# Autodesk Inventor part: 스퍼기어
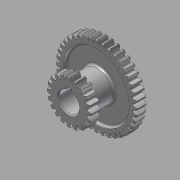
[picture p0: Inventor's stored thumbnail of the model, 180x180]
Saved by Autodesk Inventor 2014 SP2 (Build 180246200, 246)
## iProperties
Created: 2015-09
Part Number: 스퍼기어
Material: 강철, 연강
Document SubType Name: Modeling
Designer: mduedu
Density: 1 g/cm^3
Appearance: 강철
Author: mduedu
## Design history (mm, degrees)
sketch "스케치1"
  geometry: C1 r 38 at (0, 0); C2 r 40 at (0, 0); C3 r 35.5 at (0, 0); 1 further point
  constraints: 3 centre point, 3 coincident
  dimensions: "d0" = 76 diameter of C1; "d2" = 2 radial gap between concentric circles of C2 C1; "d3" = 71 diameter of C3 (computed from d0)
extrude "돌출1" new body sketch "스케치1" stored distance "d4" = 10; taper "d5" = 0 deg
sketch "스케치2"
  geometry: L1 (0, 35.5)-(0, -35.5); L2 (0, 0)-(40, 0); L3 (0, 0.57)-(39.996, 0.57); L4 (0, 1.57)-(39.969, 1.57); L5 (0, 2.07)-(39.946, 2.07); A1 r 35.5 centre (0, 0) between (0, 35.5) and (0, -35.5) reference; A2 r 40 centre (0, 0) between (40, 0) and (39.946, 2.07) reference; A3 r 9.234 centre (34.93, -7.149) between (39.996, 0.57) and (35.44, 2.07); A4 r 9.234 centre (34.93, 7.149) between (35.44, -2.07) and (39.996, -0.57); A5 r 40 centre (0, 0) between (39.996, -0.57) and (39.996, 0.57); A6 r 35.5 centre (0, 0) between (35.44, -2.07) and (35.44, 2.07); 4 further points
  constraints: 16 point on circle, 10 end point, 6 point on line, 4 centre point, 3 coincident, 3 parallel, 3 symmetric about line, 2 midpoint, 1 perpendicular, 1 vertical, 3 other
  dimensions: "d6" = 0.5 distance between parallel lines of L4 L5; "d8" = 1 distance between parallel lines of L3 L4; "d9" = 1.57 distance between parallel lines of L2 L4
extrude "돌출2" join sketch "스케치2" distance "d10" = 5; taper "d12" = 0 deg; dims "d11" = 5, "d13" = 0
fillet "모깎기1" dims "d17" = 0.5
chamfer "모따기1" distance "d21" = 1; stored, may be unused: second distance "d22" = 2, angle "d23" = 45 deg
sketch "스케치3"
  geometry: C1 r 32.5 at (0, 0); C2 r 15 at (0, 0); 1 further point
  constraints: 2 centre point, 2 coincident
  dimensions: "d27" = 65 diameter of C1; "d28" = 30 diameter of C2
extrude "돌출3" cut sketch "스케치3" distance "d29" = 3; taper "d30" = 0 deg
fillet "모깎기2" dims "d31" = 2
node "작업 평면2"
  node "작업 평면1"
sketch "스케치4"
  geometry: C1 r 15 at (0, 0) reference; 1 further point
extrude "돌출4" join sketch "스케치4" stored distance "d34" = 3; taper "d35" = 0 deg
sketch "스케치5"
  geometry: C1 r 17.5 at (0, 0); C2 r 20 at (0, 0); C3 r 22 at (0, 0); 1 further point
  constraints: 3 centre point, 3 coincident
  dimensions: "d36" = 40 diameter of C2; "d38" = 2 radial gap between concentric circles of C2 C3; "d39" = 35 diameter of C1 (= d36 - 2.5 x d38)
extrude "돌출6" join sketch "스케치5" distance "d46" = 10; taper "d47" = 0 deg
sketch "스케치6"
  geometry: L1 (0, 0)-(0, 22); L2 (-17.5, 0)-(17.5, 0); L3 (-0.57, 0)-(-0.57, 21.993); L4 (-1.57, 0)-(-1.57, 21.944); L5 (-2.07, 0)-(-2.07, 21.902); A1 r 22 centre (0, 0) between (0, 22) and (-0.57, 21.993) reference; A2 r 17.5 centre (0, 0) between (-17.5, 0) and (17.5, 0) reference; A3 r 9.431 centre (7.348, 16.868) between (-0.57, 21.993) and (-2.07, 17.377); A4 r 9.431 centre (-7.348, 16.868) between (2.07, 17.377) and (0.57, 21.993); A5 r 17.5 centre (0, 0) between (2.07, 17.377) and (-2.07, 17.377); A6 r 22 centre (0, 0) between (0.57, 21.993) and (-0.57, 21.993); 4 further points
  constraints: 16 point on circle, 10 end point, 5 point on line, 4 centre point, 3 coincident, 3 symmetric about line, 2 parallel, 2 perpendicular, 1 midpoint, 1 vertical, 3 other
  dimensions: "d40" = 0.5 distance between parallel lines of L4 L5; "d42" = 1 distance between parallel lines of L3 L4; "d43" = 1.57 distance between parallel lines of L1 L4
extrude "돌출5" join sketch "스케치6" distance "d44" = 10; taper "d45" = 0 deg
fillet "모깎기3" dims "d48" = 0.5
chamfer "모따기2" distance "d49" = 1; stored, may be unused: second distance "d50" = 2, angle "d51" = 45 deg
sketch "스케치7"
  geometry: C1 r 10 at (0, 0); 1 further point
  constraints: 1 centre point, 1 coincident
  dimensions: "d55" = 20 diameter of C1
extrude "돌출7" cut sketch "스케치7" stored distance "d56" = 10; taper "d57" = 0 deg
sketch "스케치8"
  geometry: L1 (-9.539, -3)-(-12.8, -3); L2 (-12.8, -3)-(-12.8, 3); L3 (-12.8, 3)-(-9.539, 3); L4 (-9.539, 3)-(-9.539, -3); A1 r 10 centre (0, 0) between (-9.539, -3) and (-9.539, 3) reference; 2 further points
  constraints: 8 end point, 3 point on circle, 2 parallel, 1 horizontal, 1 horizontal alignment, 1 perpendicular
  dimensions: "d58" = 6 distance of L1.end L2.end; "d60" = 22.8 distance from line of point (10, 0) L2
extrude "돌출8" cut sketch "스케치8" stored distance "d61" = 10; taper "d62" = 0 deg
chamfer "모따기3" distance "d63" = 1; stored, may be unused: second distance "d64" = 2, angle "d65" = 45 deg
fillet "모깎기4" dims "d66" = 2
node "솔리드1"
pattern_circular "원형 패턴3" dims "d25" = 360 deg
mirror "대칭1"
pattern_circular "원형 패턴4" dims "d53" = 360 deg
other parameters: "d32" = 5, "d33" = 42
